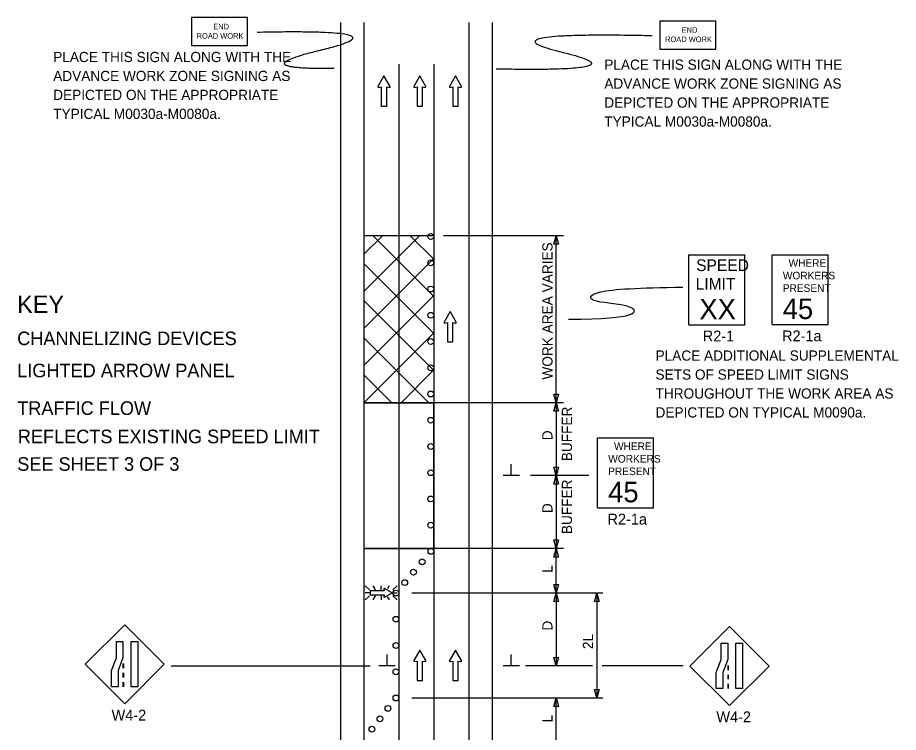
# Model space of a CAD drawing. Extents: x 16758 to 19504, y 5731 to 6944.
# Drawn here: x 17837 to 18442, y 6433 to 6923 of the extents above; entities that cross this region are included whole.
import ezdxf

# ---------------------------------------------------------------- set-up
doc = ezdxf.new("R2010")
doc.units = 0
for name, color, linetype in [('ALI_LEGAL_EX', 7, 'Continuous'), ('MT_SCRATCH_LEVEL_A', 7, 'Continuous'), ('MT_SCRATCH_LEVEL_E', 7, 'Continuous'), ('PAVT_EDGE_EX', 7, 'Continuous'), ('TRAFFIC_SIGNS_PR', 7, 'Continuous'), ('TYPICAL_TEXT_DIMEN_EX', 7, 'Continuous'), ('TYPICAL_TEXT_DIMEN_PR', 7, 'Continuous')]:
    doc.layers.add(name, color=color, linetype=linetype)

msp = doc.modelspace()

# ---------------------------------------------------------------- linework, layer by layer
at = {"layer": 'ALI_LEGAL_EX'}
for p, q in [((18099.1, 6891.16), (18099.1, 6061.98)), ((18123.1, 6891.16), (18123.1, 6061.98)), ((18123.1, 6891.16), (18123.1, 6061.98))]:
    msp.add_line(p, q, dxfattribs=at)
for points in [[(18099.1, 6891.16), (18099.1, 6866.16)], [(18123.1, 6891.16), (18123.1, 6866.16)], [(18099.1, 6791.16), (18099.1, 6766.16)], [(18123.1, 6791.16), (18123.1, 6766.16)], [(18099.1, 6691.16), (18099.1, 6666.16)], [(18123.1, 6691.16), (18123.1, 6666.16)], [(18123.1, 6591.16), (18123.1, 6566.16)], [(18099.1, 6491.16), (18099.1, 6466.16)], [(18123.1, 6491.16), (18123.1, 6466.16)]]:
    msp.add_lwpolyline(points, dxfattribs=at)
at = {"layer": 'MT_SCRATCH_LEVEL_A'}
for p, q in [((18123.1, 6773.54), (18075.1, 6773.54)), ((18123.1, 6559.01), (18075.1, 6559.01))]:
    msp.add_line(p, q, dxfattribs=at)
at = {"layer": 'MT_SCRATCH_LEVEL_E'}
for p, q in [((18088.86, 6883.24), (18084.75, 6876)), ((18088.86, 6883.24), (18084.75, 6876)), ((18093.01, 6876), (18088.86, 6883.24)), ((18093.01, 6876), (18088.86, 6883.24)), ((18113.42, 6883.24), (18109.31, 6876)), ((18113.42, 6883.24), (18109.31, 6876)), ((18117.57, 6876), (18113.42, 6883.24)), ((18117.57, 6876), (18113.42, 6883.24)), ((18137.98, 6883.24), (18133.87, 6876)), ((18137.98, 6883.24), (18133.87, 6876)), ((18142.12, 6876), (18137.98, 6883.24)), ((18142.12, 6876), (18137.98, 6883.24)), ((18085.23, 6875.32), (18087.01, 6875.64)), ((18085.23, 6875.32), (18087.01, 6875.64)), ((18087.01, 6875.64), (18087.01, 6862.38)), ((18087.01, 6875.64), (18087.01, 6862.38)), ((18090.75, 6862.38), (18090.75, 6875.64)), ((18090.75, 6875.64), (18092.53, 6875.32)), ((18090.75, 6862.38), (18090.75, 6875.64)), ((18090.75, 6875.64), (18092.53, 6875.32)), ((18109.79, 6875.32), (18111.57, 6875.64)), ((18109.79, 6875.32), (18111.57, 6875.64)), ((18111.57, 6875.64), (18111.57, 6862.38)), ((18111.57, 6875.64), (18111.57, 6862.38)), ((18115.31, 6862.38), (18115.31, 6875.64)), ((18115.31, 6875.64), (18117.09, 6875.32)), ((18115.31, 6862.38), (18115.31, 6875.64)), ((18115.31, 6875.64), (18117.09, 6875.32)), ((18134.35, 6875.32), (18136.13, 6875.64)), ((18134.35, 6875.32), (18136.13, 6875.64)), ((18136.13, 6875.64), (18136.13, 6862.38)), ((18136.13, 6875.64), (18136.13, 6862.38)), ((18139.87, 6862.38), (18139.87, 6875.64)), ((18139.87, 6875.64), (18141.65, 6875.32)), ((18139.87, 6862.38), (18139.87, 6875.64)), ((18139.87, 6875.64), (18141.65, 6875.32)), ((18087.01, 6862.38), (18090.75, 6862.38)), ((18087.01, 6862.38), (18090.75, 6862.38)), ((18111.57, 6862.38), (18115.31, 6862.38)), ((18111.57, 6862.38), (18115.31, 6862.38)), ((18136.13, 6862.38), (18139.87, 6862.38)), ((18136.13, 6862.38), (18139.87, 6862.38)), ((18134.32, 6721.55), (18130.21, 6714.31)), ((18134.32, 6721.55), (18130.21, 6714.31)), ((18138.46, 6714.31), (18134.32, 6721.55)), ((18138.46, 6714.31), (18134.32, 6721.55)), ((18130.69, 6713.62), (18132.47, 6713.94)), ((18130.69, 6713.62), (18132.47, 6713.94)), ((18132.47, 6713.94), (18132.47, 6700.68)), ((18132.47, 6713.94), (18132.47, 6700.68)), ((18136.21, 6700.68), (18136.21, 6713.94)), ((18136.21, 6713.94), (18137.98, 6713.62)), ((18136.21, 6700.68), (18136.21, 6713.94)), ((18136.21, 6713.94), (18137.98, 6713.62)), ((18132.47, 6700.68), (18136.21, 6700.68)), ((18132.47, 6700.68), (18136.21, 6700.68)), ((18113.42, 6489.34), (18109.31, 6482.1)), ((18113.42, 6489.34), (18109.31, 6482.1)), ((18117.57, 6482.1), (18113.42, 6489.34)), ((18117.57, 6482.1), (18113.42, 6489.34)), ((18137.98, 6489.34), (18133.87, 6482.1)), ((18137.98, 6489.34), (18133.87, 6482.1)), ((18142.12, 6482.1), (18137.98, 6489.34)), ((18142.12, 6482.1), (18137.98, 6489.34)), ((18109.79, 6481.41), (18111.57, 6481.73)), ((18109.79, 6481.41), (18111.57, 6481.73)), ((18111.57, 6481.73), (18111.57, 6468.47)), ((18111.57, 6481.73), (18111.57, 6468.47)), ((18115.31, 6468.47), (18115.31, 6481.73)), ((18115.31, 6481.73), (18117.09, 6481.41)), ((18115.31, 6468.47), (18115.31, 6481.73)), ((18115.31, 6481.73), (18117.09, 6481.41)), ((18134.35, 6481.41), (18136.13, 6481.73)), ((18134.35, 6481.41), (18136.13, 6481.73)), ((18136.13, 6481.73), (18136.13, 6468.47)), ((18136.13, 6481.73), (18136.13, 6468.47)), ((18139.87, 6468.47), (18139.87, 6481.73)), ((18139.87, 6481.73), (18141.65, 6481.41)), ((18139.87, 6468.47), (18139.87, 6481.73)), ((18139.87, 6481.73), (18141.65, 6481.41)), ((18111.57, 6468.47), (18115.31, 6468.47)), ((18111.57, 6468.47), (18115.31, 6468.47)), ((18136.13, 6468.47), (18139.87, 6468.47)), ((18136.13, 6468.47), (18139.87, 6468.47))]:
    msp.add_line(p, q, dxfattribs=at)
for centre, start, end in [((18085.16, 6875.78), 150.42484, 279.96381), ((18085.16, 6875.78), 150.42484, 279.96381), ((18092.6, 6875.78), 260.03619, 29.77312), ((18092.6, 6875.78), 260.03619, 29.77312), ((18109.72, 6875.78), 150.42484, 279.96381), ((18109.72, 6875.78), 150.42484, 279.96381), ((18117.16, 6875.78), 260.03619, 29.77312), ((18117.16, 6875.78), 260.03619, 29.77312), ((18134.27, 6875.78), 150.42484, 279.96381), ((18134.27, 6875.78), 150.42484, 279.96381), ((18141.72, 6875.78), 260.03619, 29.77312), ((18141.72, 6875.78), 260.03619, 29.77312), ((18130.61, 6714.08), 150.42484, 279.96381), ((18130.61, 6714.08), 150.42484, 279.96381), ((18138.05, 6714.08), 260.03619, 29.77312), ((18138.05, 6714.08), 260.03619, 29.77312), ((18109.72, 6481.87), 150.42484, 279.96381), ((18109.72, 6481.87), 150.42484, 279.96381), ((18117.16, 6481.87), 260.03619, 29.77312), ((18117.16, 6481.87), 260.03619, 29.77312), ((18134.27, 6481.87), 150.42484, 279.96381), ((18134.27, 6481.87), 150.42484, 279.96381), ((18141.72, 6481.87), 260.03619, 29.77312), ((18141.72, 6481.87), 260.03619, 29.77312)]:
    msp.add_arc(centre, 0.463, start, end, dxfattribs=at)
at = {"layer": 'PAVT_EDGE_EX'}
for p, q in [((18059.1, 6919.77), (18059.1, 6061.98)), ((18075.1, 6919.77), (18075.1, 6061.98)), ((18147.1, 6919.77), (18147.1, 6061.98)), ((18163.1, 6919.77), (18163.1, 6061.98)), ((18075.1, 6891.16), (18075.1, 6061.98)), ((18075.1, 6760.83), (18087.81, 6773.54)), ((18075.1, 6735.38), (18113.27, 6773.54)), ((18123.1, 6731.92), (18081.48, 6773.54)), ((18123.1, 6757.38), (18106.93, 6773.54)), ((18075.1, 6709.92), (18123.1, 6757.92)), ((18123.1, 6706.47), (18075.1, 6754.47)), ((18075.1, 6684.46), (18123.1, 6732.46)), ((18123.1, 6681.01), (18075.1, 6729.01)), ((18075.1, 6659.01), (18123.1, 6707.01)), ((18119.65, 6659.01), (18075.1, 6703.56)), ((18075.1, 6702.97), (18075.1, 6588.44)), ((18100.56, 6659.01), (18123.1, 6681.55)), ((18094.19, 6659.01), (18075.1, 6678.1)), ((18075.1, 6659.01), (18123.1, 6659.01)), ((18075.1, 6588.44), (18075.1, 6559.01)), ((18123.02, 6586.33), (18123.07, 6586.25)), ((18123.06, 6584.93), (18123.1, 6585.01)), ((18123.02, 6579.04), (18123.07, 6578.96)), ((18123.06, 6577.64), (18123.1, 6577.73)), ((18123.02, 6571.76), (18123.07, 6571.68)), ((18123.06, 6570.36), (18123.1, 6570.44)), ((18075.1, 6559.01), (18123.1, 6559.01))]:
    msp.add_line(p, q, dxfattribs=at)
msp.add_lwpolyline([(18123.1, 6659.01), (18075.1, 6659.01), (18075.1, 6559.01), (18123.1, 6559.01)], close=True, dxfattribs=at)
at = {"layer": 'TRAFFIC_SIGNS_PR'}
for p, q in [((18298.05, 6760.45), (18336.45, 6760.45)), ((18298.05, 6712.45), (18298.05, 6760.45)), ((18336.45, 6712.45), (18336.45, 6760.45)), ((18355.24, 6760.54), (18393.64, 6760.54)), ((18355.24, 6712.54), (18355.24, 6760.54)), ((18393.64, 6712.54), (18393.64, 6760.54)), ((18298.05, 6712.45), (18336.45, 6712.45)), ((18355.24, 6712.54), (18393.64, 6712.54)), ((18235.43, 6634.85), (18273.83, 6634.85)), ((18235.43, 6586.85), (18235.43, 6634.85)), ((18273.83, 6586.85), (18273.83, 6634.85)), ((18235.43, 6586.85), (18273.83, 6586.85)), ((18078.87, 6530.55), (18076.05, 6533.37)), ((18078.87, 6528.52), (18076.05, 6528.52)), ((18081.17, 6533.37), (18082.8, 6530.55)), ((18086.96, 6530.55), (18086.96, 6533.37)), ((18092.43, 6533.37), (18091.22, 6531.27)), ((18097.86, 6533.36), (18095.04, 6530.55)), ((18095.04, 6528.52), (18097.86, 6528.52)), ((18078.87, 6526.48), (18076.05, 6523.66)), ((18082.82, 6526.48), (18081.2, 6523.66)), ((18086.96, 6526.48), (18086.96, 6523.66)), ((18091.14, 6525.85), (18092.4, 6523.66)), ((18097.86, 6523.66), (18095.04, 6526.48)), ((17910.97, 6506.68), (17883.81, 6479.53)), ((17938.12, 6479.53), (17910.97, 6506.68)), ((18326.05, 6505.5), (18298.89, 6478.35)), ((18353.2, 6478.35), (18326.05, 6505.5)), ((17909.72, 6480.02), (17909.72, 6476.82)), ((17910.12, 6480.02), (17910.12, 6476.82)), ((17883.81, 6479.53), (17910.97, 6452.38)), ((17910.97, 6452.38), (17938.12, 6479.53)), ((18298.89, 6478.35), (18326.05, 6451.2)), ((18324.8, 6478.84), (18324.8, 6475.64)), ((18325.2, 6478.84), (18325.2, 6475.64)), ((18326.05, 6451.2), (18353.2, 6478.35)), ((17909.72, 6473.62), (17909.72, 6470.42)), ((17910.12, 6473.62), (17910.12, 6470.42)), ((18324.8, 6472.44), (18324.8, 6469.24)), ((18325.2, 6472.44), (18325.2, 6469.24)), ((17909.72, 6467.22), (17909.72, 6464.02)), ((17910.12, 6467.22), (17910.12, 6464.02)), ((18324.8, 6466.04), (18324.8, 6462.84)), ((18325.2, 6466.04), (18325.2, 6462.84))]:
    msp.add_line(p, q, dxfattribs=at)
for points in [[(17956.7, 6903.95), (17995.1, 6903.95), (17995.1, 6923.15), (17956.7, 6923.15)], [(18278.18, 6901.61), (18316.58, 6901.61), (18316.58, 6920.81), (18278.18, 6920.81)], [(17909.72, 6495.27), (17909.72, 6484.09), (17906.38, 6475.2), (17906.38, 6464.02), (17901.88, 6464.02), (17901.88, 6475.2), (17905.23, 6484.09), (17905.23, 6495.27)], [(17919.86, 6495.27), (17919.86, 6464.02), (17915.36, 6464.02), (17915.36, 6495.27)], [(18324.8, 6494.09), (18324.8, 6482.91), (18321.45, 6474.02), (18321.45, 6462.84), (18316.96, 6462.84), (18316.96, 6474.02), (18320.31, 6482.91), (18320.31, 6494.09)], [(18334.93, 6494.09), (18334.93, 6462.84), (18330.44, 6462.84), (18330.44, 6494.09)]]:
    msp.add_lwpolyline(points, close=True, dxfattribs=at)
for points in [[(18088.79, 6531.2), (18089.02, 6529.9), (18079.29, 6529.9), (18079.29, 6527.16), (18089.02, 6527.16), (18088.78, 6525.85)], [(18089.29, 6525.5), (18094.6, 6528.52), (18089.29, 6531.56)]]:
    msp.add_lwpolyline(points, dxfattribs=at)
for centre in [(18121, 6772.96), (18121, 6754.96), (18121, 6736.96), (18121, 6718.96), (18121, 6700.96), (18121, 6682.96), (18121, 6664.96), (18121, 6646.96), (18121, 6628.96), (18121, 6610.96), (18121, 6592.96), (18121, 6574.96), (18121.1, 6557.01), (18115.1, 6549.87), (18109.1, 6542.73), (18103.1, 6535.59), (18097.1, 6528.44), (18097.1, 6510.44), (18097.1, 6492.44), (18097.1, 6474.44), (18097.1, 6456.44), (18091.6, 6449.31), (18086.1, 6442.19), (18080.61, 6435.06)]:
    msp.add_circle(centre, 2, dxfattribs=at)
for centre, start, end in [((18089.12, 6531.26), 61.48329, 189.95933), ((18089.12, 6525.8), 170.73078, 298.89165)]:
    msp.add_arc(centre, 0.341, start, end, dxfattribs=at)
for points in [[(18054.8, 6888.18), (17990.28, 6887.61), (18104.19, 6915.19), (18001.77, 6913.02)], [(18273, 6910.65), (18154.05, 6913.29), (18267.96, 6885.71), (18165.79, 6887.88)]]:
    msp.add_open_spline(points, degree=2, dxfattribs=at)
at = {"layer": 'TYPICAL_TEXT_DIMEN_PR'}
for p, q in [((18212.1, 6773.54), (18129.7, 6773.54)), ((18205.53, 6767.68), (18207.1, 6773.54)), ((18207.1, 6659.01), (18207.1, 6773.54)), ((18207.1, 6773.54), (18208.67, 6767.68)), ((18207.1, 6767.68), (18205.53, 6767.68)), ((18208.67, 6767.68), (18207.1, 6767.68)), ((18207.1, 6659.01), (18205.53, 6664.87)), ((18205.53, 6664.87), (18207.1, 6664.87)), ((18207.1, 6664.87), (18208.67, 6664.87)), ((18208.67, 6664.87), (18207.1, 6659.01)), ((18212.1, 6659.01), (18075.1, 6659.01)), ((18205.53, 6653.15), (18207.1, 6659.01)), ((18207.1, 6659.01), (18207.1, 6609.01)), ((18207.1, 6659.01), (18208.67, 6653.15)), ((18207.1, 6653.15), (18205.53, 6653.15)), ((18208.67, 6653.15), (18207.1, 6653.15)), ((18176.22, 6609.01), (18176.22, 6616.79)), ((18207.1, 6609.01), (18205.53, 6614.87)), ((18205.53, 6614.87), (18207.1, 6614.87)), ((18207.1, 6614.87), (18208.67, 6614.87)), ((18208.67, 6614.87), (18207.1, 6609.01)), ((18181.85, 6609.01), (18170.6, 6609.01)), ((18229.49, 6609.01), (18189.36, 6609.01)), ((18205.53, 6603.15), (18207.1, 6609.01)), ((18207.1, 6609.01), (18207.1, 6559.01)), ((18207.1, 6609.01), (18208.67, 6603.15)), ((18207.1, 6603.15), (18205.53, 6603.15)), ((18208.67, 6603.15), (18207.1, 6603.15)), ((18207.1, 6559.01), (18205.53, 6564.87)), ((18205.53, 6564.87), (18207.1, 6564.87)), ((18207.1, 6564.87), (18208.67, 6564.87)), ((18208.67, 6564.87), (18207.1, 6559.01)), ((18212.1, 6559.01), (18123.1, 6559.01)), ((18205.53, 6553.15), (18207.1, 6559.01)), ((18207.1, 6528.44), (18207.1, 6559.01)), ((18207.1, 6559.01), (18208.67, 6553.15)), ((18207.1, 6553.15), (18205.53, 6553.15)), ((18208.67, 6553.15), (18207.1, 6553.15)), ((18239.14, 6528.44), (18108, 6528.44)), ((18207.1, 6528.44), (18205.53, 6534.31)), ((18205.53, 6534.31), (18207.1, 6534.31)), ((18205.53, 6522.58), (18207.1, 6528.44)), ((18207.1, 6534.31), (18208.67, 6534.31)), ((18208.67, 6534.31), (18207.1, 6528.44)), ((18207.1, 6528.44), (18207.1, 6478.44)), ((18207.1, 6528.44), (18208.67, 6522.58)), ((18233.34, 6522.58), (18234.91, 6528.44)), ((18234.91, 6528.44), (18236.48, 6522.58)), ((18234.91, 6528.44), (18234.91, 6456.44)), ((18207.1, 6522.58), (18205.53, 6522.58)), ((18208.67, 6522.58), (18207.1, 6522.58)), ((18234.91, 6522.58), (18233.34, 6522.58)), ((18236.48, 6522.58), (18234.91, 6522.58)), ((18091.03, 6478.44), (18091.03, 6486.23)), ((18176.22, 6478.44), (18176.22, 6486.23)), ((18207.1, 6478.44), (18205.53, 6484.31)), ((18205.53, 6484.31), (18207.1, 6484.31)), ((18207.1, 6484.31), (18208.67, 6484.31)), ((18208.67, 6484.31), (18207.1, 6478.44)), ((18234.91, 6483.31), (18234.91, 6479.55)), ((17942.78, 6478.44), (18079.3, 6478.44)), ((18096.65, 6478.44), (18085.4, 6478.44)), ((18181.85, 6478.44), (18170.6, 6478.44)), ((18231.92, 6478.44), (18186.1, 6478.44)), ((18294.18, 6478.44), (18238.54, 6478.44)), ((18234.91, 6456.44), (18233.34, 6462.31)), ((18233.34, 6462.31), (18234.91, 6462.31)), ((18234.91, 6462.31), (18236.48, 6462.31)), ((18236.48, 6462.31), (18234.91, 6456.44)), ((18108, 6456.44), (18239.14, 6456.44)), ((18205.53, 6450.58), (18207.1, 6456.44)), ((18207.1, 6425.88), (18207.1, 6456.44)), ((18207.1, 6456.44), (18208.67, 6450.58)), ((18207.1, 6450.58), (18205.53, 6450.58)), ((18208.67, 6450.58), (18207.1, 6450.58))]:
    msp.add_line(p, q, dxfattribs=at)
msp.add_open_spline([(18215.48, 6716.28), (18263.95, 6716.28), (18263.95, 6727.03), (18229.03, 6727.03), (18229.03, 6736.08), (18263.23, 6737.84), (18294.04, 6738.26)], degree=3, dxfattribs=at)

# ---------------------------------------------------------------- texts
at = {"layer": 'TRAFFIC_SIGNS_PR'}
for s, height, p in [('END', 3.831, (17971.7, 6915.08)), ('END', 3.831, (18293.18, 6912.74)), ('ROAD WORK', 3.831, (17960.31, 6908.7)), ('ROAD WORK', 3.831, (18281.79, 6906.35)), ('PLACE THIS SIGN ALONG WITH THE', 7, (17861.87, 6892.65)), ('PLACE THIS SIGN ALONG WITH THE', 7, (18240.07, 6887.4)), ('ADVANCE WORK ZONE SIGNING AS', 7, (17861.87, 6879.65)), ('ADVANCE WORK ZONE SIGNING AS', 7, (18240.07, 6874.4)), ('DEPICTED ON THE APPROPRIATE', 7, (17861.87, 6866.65)), ('DEPICTED ON THE APPROPRIATE', 7, (18240.07, 6861.4)), ('TYPICAL M0030a-M0080a.', 7, (17861.87, 6853.65)), ('TYPICAL M0030a-M0080a.', 7, (18240.07, 6848.4)), ('SPEED', 8, (18303.08, 6749.31)), ('WHERE', 5.2, (18366.56, 6752.22)), ('WORKERS', 5.2, (18362.63, 6743.62)), ('LIMIT', 8, (18302.75, 6736.51)), ('PRESENT', 5.2, (18362.56, 6735.02)), ('XX', 14.031, (18305.36, 6716.21)), ('45', 14.031, (18362.55, 6716.39)), ('R2-1', 7.44, (18307.66, 6701.01)), ('R2-1a', 7.44, (18362.1, 6701.1)), ('PLACE ADDITIONAL SUPPLEMENTAL', 7, (18275.25, 6687.84)), ('SETS OF SPEED LIMIT SIGNS', 7, (18275.25, 6674.84)), ('THROUGHOUT THE WORK AREA AS', 7, (18275.25, 6661.84)), ('DEPICTED ON TYPICAL M0090a.', 7, (18275.25, 6648.84)), ('WHERE', 5.2, (18246.74, 6626.53)), ('WORKERS', 5.2, (18242.81, 6617.93)), ('PRESENT', 5.2, (18242.74, 6609.33)), ('45', 14.031, (18242.74, 6590.7)), ('R2-1a', 7.44, (18242.28, 6575.41)), ('W4-2', 7.44, (17901.92, 6440.94)), ('W4-2', 7.44, (18317, 6439.76))]:
    msp.add_text(s, height=height, dxfattribs=at).set_placement(p)
at = {"layer": 'TYPICAL_TEXT_DIMEN_EX'}
for s, height, p in [('KEY', 12, (17837.16, 6720.53)), ('CHANNELIZING DEVICES', 9.3, (17837.16, 6698.48)), ('LIGHTED ARROW PANEL', 9.3, (17837.16, 6676.43)), ('TRAFFIC FLOW', 9.3, (17837.16, 6650.63)), ('REFLECTS EXISTING SPEED LIMIT', 9.3, (17837.58, 6631.2)), ('SEE SHEET 3 OF 3', 9.3, (17837.2, 6612.3))]:
    msp.add_text(s, height=height, dxfattribs=at).set_placement(p)
at = {"layer": 'TYPICAL_TEXT_DIMEN_PR'}
for s, p in [('WORK AREA VARIES', (18204.54, 6674.86)), ('BUFFER', (18217.91, 6618.87)), ('D', (18204.54, 6633.23)), ('BUFFER', (18217.91, 6568.87)), ('D', (18204.54, 6583.23)), ('L', (18204.54, 6542.3)), ('D', (18204.54, 6502.66)), ('2L', (18232.35, 6489.95)), ('L', (18204.54, 6439.74))]:
    msp.add_text(s, height=7, rotation=90, dxfattribs=at).set_placement(p)

doc.saveas('drawing.dxf')
